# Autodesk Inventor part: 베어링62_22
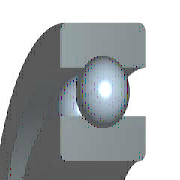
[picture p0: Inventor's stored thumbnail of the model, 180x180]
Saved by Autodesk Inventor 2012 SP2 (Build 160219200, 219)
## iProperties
Created: 2009-02
Part Number: 베어링62_22
Material: 강, 연강
Description: 깊은 그루브 볼 베어링
Document SubType Name: Modeling
Standard: KS B 2023
Designer: KYOUNG IL JANG
Standards Organization: KS
Language: ko-KR
Size Designation: 62/22 - 22 x 50 x 14
Categories: <MemberInstance><Categories><Category DisplayName="샤프트 부품" InternalName="7f7aeb1f-a693-4053-b835-cee3144e0d98" Mnemonic="SHFT"><Category DisplayName="베어링" Inter
Density: 1 g/cm^3
IsCustomPart: 0
Author: KYOUNG IL JANG
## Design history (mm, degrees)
revolve "본체" stored, may be unused: angle "d6" = 90 deg
revolve "볼" stored, may be unused: angle "d7" = 90 deg
pattern_circular "IDS_ARRAYBALL[SIMPL:T]" dims angle "d3" = 360 deg
body "Solid1"
sketch "스케치" dims "d0" = 7.28 (= -0.26 x WD + 0.26 x BD)
  geometry: L1 (3.36, 18)-(10.64, 18); L2 (7, 18)-(7, 14.36); L3 (7, 18)-(7, 21.64); L4 (4.295, 15.564)-(0, 15.564); L5 (0, 11)-(14, 11); L6 (4.295, 20.436)-(0, 20.436); L7 (0, 25)-(14, 25); L8 (14, 11)-(14, 15.564); L9 (9.705, 15.564)-(14, 15.564); L10 (9.705, 20.436)-(14, 20.436); L11 (14, 25)-(14, 20.436); L12 (-1.4, 0)-(8.4, 0) reference; L13 (0, -0.3)-(0, 5.3) reference
  constraints: 22 end point, 4 point on line, 2 collinear, 2 perpendicular, 2 symmetric about line, 1 midpoint, 1 parallel, 14 other
  dimensions: "d9" = 22 diameter of L5 L12 (= WD); "d11" = 50 diameter of L7 L12 (= BD); "d12" = 14 distance between parallel lines of L8 L13 (= KB); "d13" = 31.128 diameter of L9 L12 (= 0.326 x BD + 0.674 x WD)
fillet "모깎기1" dims "d1" = 1 (= KRS)
other parameters: "WD" = 22 [user parameter; used in 5 equation terms], "BD" = 50 [user parameter; used in 5 equation terms], "KB" = 14 [user parameter; used in 1 equation term], "KRS" = 1 [user parameter; used in 1 equation term], "d4" = 0, "d5" = 0, "d8" = 0, "d14" = 0, "d15" = 0, "BBA" = 0 [user parameter], "BC0" = 7154000 [user parameter], "BC" = 1.2233e+07 [user parameter], "BR" = 25 (= 0.5 x BD) [user parameter], "WR" = 11 (= 0.5 x WD) [user parameter]
